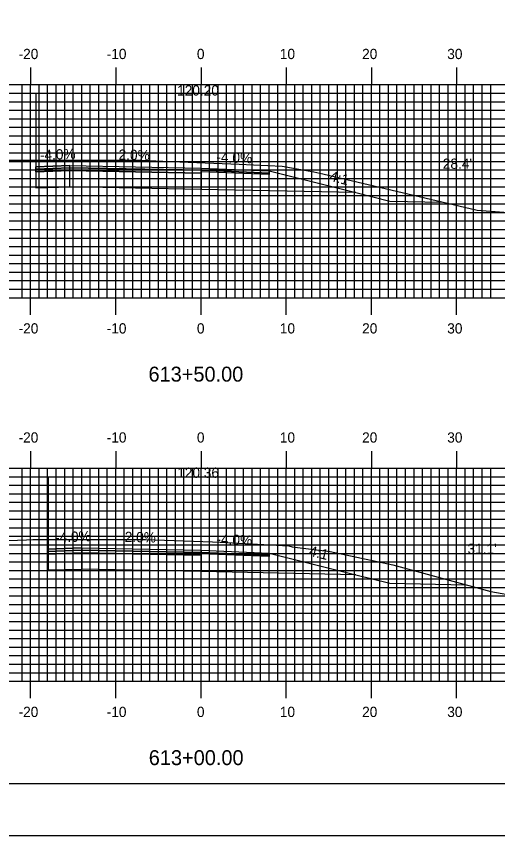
# Model space of a CAD drawing. Extents: x 844143 to 844486, y 363538 to 363758.
# Drawn here: x 844286.8 to 844343.3, y 363537.6 to 363633.7 of the extents above; entities that cross this region are included whole.
import ezdxf

# ---------------------------------------------------------------- set-up
doc = ezdxf.new("R2010")
doc.units = 0
for name, color, linetype in [('ANNOTATION', 7, 'Continuous'), ('BORDER', 7, 'Continuous'), ('D_Roadway_Centerline', 7, 'Continuous'), ('D_Roadway_Centerline_Text', 7, 'Continuous'), ('D_Roadway_Edge_Shoulder', 7, 'Continuous'), ('D_Roadway_Edge_TW', 7, 'Continuous'), ('D_Roadway_FinishedGrade', 7, 'Continuous'), ('D_Roadway_Pavement', 7, 'Continuous'), ('D_Roadway_SubGrade', 7, 'Continuous'), ('D_Text_Standard', 7, 'Continuous'), ('H_V ANNOTATION', 7, 'Continuous'), ('M_Roadway_Centerline', 7, 'Continuous'), ('MAJOR', 7, 'Continuous'), ('MINOR', 7, 'Continuous'), ('PLOT BOUNDARY', 7, 'Continuous'), ('S_Roadway_Centerline', 7, 'Continuous')]:
    doc.layers.add(name, color=color, linetype=linetype)

msp = doc.modelspace()

# ---------------------------------------------------------------- linework, layer by layer
at = {"layer": 'BORDER'}
msp.add_lwpolyline([(844158.85, 363543.721), (844478.85, 363543.721), (844478.85, 363753.721), (844158.85, 363753.721)], close=True, dxfattribs=at)
at = {"layer": 'D_Roadway_Centerline'}
for points in [[(844289.067, 363616.066), (844293.067, 363616.226), (844308.45, 363615.918), (844316.45, 363615.598), (844326.624, 363613.055)], [(844290.512, 363571.199), (844294.512, 363571.359), (844308.45, 363571.08), (844316.45, 363570.76), (844326.624, 363568.217)]]:
    msp.add_lwpolyline(points, dxfattribs=at)
at = {"layer": 'D_Roadway_Edge_Shoulder'}
for points in [[(844293.067, 363616.226), (844289.067, 363616.066), (844289.067, 363615.816), (844293.067, 363615.976)], [(844308.45, 363615.918), (844316.45, 363615.598), (844316.45, 363615.348), (844308.45, 363615.668)], [(844294.512, 363571.359), (844290.512, 363571.199), (844290.512, 363570.949), (844294.512, 363571.109)], [(844308.45, 363571.08), (844316.45, 363570.76), (844316.45, 363570.51), (844308.45, 363570.83)]]:
    msp.add_lwpolyline(points, close=True, dxfattribs=at)
at = {"layer": 'D_Roadway_Edge_TW'}
for points in [[(844293.067, 363616.226), (844308.45, 363615.918), (844308.45, 363615.668), (844293.067, 363615.976)], [(844294.512, 363571.359), (844308.45, 363571.08), (844308.45, 363570.83), (844294.512, 363571.109)]]:
    msp.add_lwpolyline(points, close=True, dxfattribs=at)
at = {"layer": 'D_Roadway_FinishedGrade'}
for points in [[(844326.624, 363613.055), (844330.624, 363612.055), (844336.808, 363611.931)], [(844326.624, 363568.217), (844330.624, 363567.217), (844339.574, 363567.038)]]:
    msp.add_lwpolyline(points, dxfattribs=at)
at = {"layer": 'D_Roadway_Pavement'}
for points in [[(844293.067, 363615.976), (844289.067, 363615.816), (844289.067, 363615.483), (844293.067, 363615.643)], [(844293.067, 363615.976), (844308.45, 363615.668), (844308.45, 363615.335), (844293.067, 363615.643)], [(844308.45, 363615.668), (844316.45, 363615.348), (844316.45, 363615.182), (844308.45, 363615.502)], [(844294.512, 363571.109), (844290.512, 363570.949), (844290.512, 363570.616), (844294.512, 363570.776)], [(844294.512, 363571.109), (844308.45, 363570.83), (844308.45, 363570.497), (844294.512, 363570.776)], [(844308.45, 363570.83), (844316.45, 363570.51), (844316.45, 363570.344), (844308.45, 363570.664)]]:
    msp.add_lwpolyline(points, close=True, dxfattribs=at)
for points in [[(844308.45, 363615.668), (844308.45, 363615.335)], [(844308.45, 363615.668), (844308.45, 363615.335)], [(844308.45, 363570.83), (844308.45, 363570.497)], [(844308.45, 363570.83), (844308.45, 363570.497)]]:
    msp.add_lwpolyline(points, dxfattribs=at)
at = {"layer": 'D_Roadway_SubGrade'}
for p, q in [((844289.067, 363624.724), (844289.067, 363613.626)), ((844290.512, 363579.713), (844290.512, 363568.616))]:
    msp.add_line(p, q, dxfattribs=at)
for points in [[(844293.067, 363615.643), (844289.067, 363615.483), (844289.067, 363615.816), (844289.067, 363616.066), (844289.067, 363613.626), (844293.067, 363613.726)], [(844293.067, 363615.643), (844308.45, 363615.335), (844308.45, 363613.418), (844293.067, 363613.726)], [(844308.45, 363615.335), (844308.45, 363615.668), (844316.45, 363615.348), (844316.45, 363615.598), (844326.624, 363613.055), (844308.45, 363613.418)], [(844294.512, 363570.776), (844290.512, 363570.616), (844290.512, 363570.949), (844290.512, 363571.199), (844290.512, 363568.779), (844294.512, 363568.859)], [(844294.512, 363570.776), (844308.45, 363570.497), (844308.45, 363568.58), (844294.512, 363568.859)], [(844308.45, 363570.497), (844308.45, 363570.83), (844316.45, 363570.51), (844316.45, 363570.76), (844326.624, 363568.217), (844308.45, 363568.58)]]:
    msp.add_lwpolyline(points, close=True, dxfattribs=at)
at = {"layer": 'MAJOR'}
for p, q in [((844288.45, 363627.725), (844288.45, 363625.721)), ((844298.45, 363627.725), (844298.45, 363625.721)), ((844308.45, 363627.725), (844308.45, 363625.721)), ((844318.45, 363627.725), (844318.45, 363625.721)), ((844328.45, 363627.725), (844328.45, 363625.721)), ((844338.45, 363627.725), (844338.45, 363625.721)), ((844168.45, 363625.721), (844448.45, 363625.721)), ((844168.45, 363625.721), (844448.45, 363625.721)), ((844288.45, 363600.721), (844288.45, 363625.721)), ((844298.45, 363600.721), (844298.45, 363625.721)), ((844308.45, 363600.721), (844308.45, 363625.721)), ((844318.45, 363600.721), (844318.45, 363625.721)), ((844328.45, 363600.721), (844328.45, 363625.721)), ((844338.45, 363600.721), (844338.45, 363625.721)), ((844168.45, 363620.721), (844448.45, 363620.721)), ((844168.45, 363615.721), (844448.45, 363615.721)), ((844168.45, 363610.721), (844448.45, 363610.721)), ((844168.45, 363605.721), (844448.45, 363605.721)), ((844168.45, 363600.721), (844448.45, 363600.721)), ((844168.45, 363600.721), (844448.45, 363600.721)), ((844288.45, 363598.717), (844288.45, 363600.721)), ((844298.45, 363598.717), (844298.45, 363600.721)), ((844308.45, 363598.717), (844308.45, 363600.721)), ((844318.45, 363598.717), (844318.45, 363600.721)), ((844328.45, 363598.717), (844328.45, 363600.721)), ((844338.45, 363598.717), (844338.45, 363600.721)), ((844288.45, 363582.725), (844288.45, 363580.721)), ((844298.45, 363582.725), (844298.45, 363580.721)), ((844308.45, 363582.725), (844308.45, 363580.721)), ((844318.45, 363582.725), (844318.45, 363580.721)), ((844328.45, 363582.725), (844328.45, 363580.721)), ((844338.45, 363582.725), (844338.45, 363580.721)), ((844168.45, 363580.721), (844448.45, 363580.721)), ((844168.45, 363580.721), (844448.45, 363580.721)), ((844288.45, 363555.721), (844288.45, 363580.721)), ((844298.45, 363555.721), (844298.45, 363580.721)), ((844308.45, 363555.721), (844308.45, 363580.721)), ((844318.45, 363555.721), (844318.45, 363580.721)), ((844328.45, 363555.721), (844328.45, 363580.721)), ((844338.45, 363555.721), (844338.45, 363580.721)), ((844168.45, 363575.721), (844448.45, 363575.721)), ((844168.45, 363570.721), (844448.45, 363570.721)), ((844168.45, 363565.721), (844448.45, 363565.721)), ((844168.45, 363560.721), (844448.45, 363560.721)), ((844168.45, 363555.721), (844448.45, 363555.721)), ((844168.45, 363555.721), (844448.45, 363555.721)), ((844288.45, 363553.717), (844288.45, 363555.721)), ((844298.45, 363553.717), (844298.45, 363555.721)), ((844308.45, 363553.717), (844308.45, 363555.721)), ((844318.45, 363553.717), (844318.45, 363555.721)), ((844328.45, 363553.717), (844328.45, 363555.721)), ((844338.45, 363553.717), (844338.45, 363555.721))]:
    msp.add_line(p, q, dxfattribs=at)
at = {"layer": 'MINOR'}
for p, q in [((844287.45, 363600.721), (844287.45, 363625.721)), ((844289.45, 363600.721), (844289.45, 363625.721)), ((844290.45, 363600.721), (844290.45, 363625.721)), ((844291.45, 363600.721), (844291.45, 363625.721)), ((844292.45, 363600.721), (844292.45, 363625.721)), ((844293.45, 363600.721), (844293.45, 363625.721)), ((844294.45, 363600.721), (844294.45, 363625.721)), ((844295.45, 363600.721), (844295.45, 363625.721)), ((844296.45, 363600.721), (844296.45, 363625.721)), ((844297.45, 363600.721), (844297.45, 363625.721)), ((844299.45, 363600.721), (844299.45, 363625.721)), ((844300.45, 363600.721), (844300.45, 363625.721)), ((844301.45, 363600.721), (844301.45, 363625.721)), ((844302.45, 363600.721), (844302.45, 363625.721)), ((844303.45, 363600.721), (844303.45, 363625.721)), ((844304.45, 363600.721), (844304.45, 363625.721)), ((844305.45, 363600.721), (844305.45, 363625.721)), ((844306.45, 363600.721), (844306.45, 363625.721)), ((844307.45, 363600.721), (844307.45, 363625.721)), ((844309.45, 363600.721), (844309.45, 363625.721)), ((844310.45, 363600.721), (844310.45, 363625.721)), ((844311.45, 363600.721), (844311.45, 363625.721)), ((844312.45, 363600.721), (844312.45, 363625.721)), ((844313.45, 363600.721), (844313.45, 363625.721)), ((844314.45, 363600.721), (844314.45, 363625.721)), ((844315.45, 363600.721), (844315.45, 363625.721)), ((844316.45, 363600.721), (844316.45, 363625.721)), ((844317.45, 363600.721), (844317.45, 363625.721)), ((844319.45, 363600.721), (844319.45, 363625.721)), ((844320.45, 363600.721), (844320.45, 363625.721)), ((844321.45, 363600.721), (844321.45, 363625.721)), ((844322.45, 363600.721), (844322.45, 363625.721)), ((844323.45, 363600.721), (844323.45, 363625.721)), ((844324.45, 363600.721), (844324.45, 363625.721)), ((844325.45, 363600.721), (844325.45, 363625.721)), ((844326.45, 363600.721), (844326.45, 363625.721)), ((844327.45, 363600.721), (844327.45, 363625.721)), ((844329.45, 363600.721), (844329.45, 363625.721)), ((844330.45, 363600.721), (844330.45, 363625.721)), ((844331.45, 363600.721), (844331.45, 363625.721)), ((844332.45, 363600.721), (844332.45, 363625.721)), ((844333.45, 363600.721), (844333.45, 363625.721)), ((844334.45, 363600.721), (844334.45, 363625.721)), ((844335.45, 363600.721), (844335.45, 363625.721)), ((844336.45, 363600.721), (844336.45, 363625.721)), ((844337.45, 363600.721), (844337.45, 363625.721)), ((844339.45, 363600.721), (844339.45, 363625.721)), ((844340.45, 363600.721), (844340.45, 363625.721)), ((844341.45, 363600.721), (844341.45, 363625.721)), ((844342.45, 363600.721), (844342.45, 363625.721)), ((844168.45, 363624.721), (844448.45, 363624.721)), ((844168.45, 363623.721), (844448.45, 363623.721)), ((844168.45, 363622.721), (844448.45, 363622.721)), ((844168.45, 363621.721), (844448.45, 363621.721)), ((844168.45, 363619.721), (844448.45, 363619.721)), ((844168.45, 363618.721), (844448.45, 363618.721)), ((844168.45, 363617.721), (844448.45, 363617.721)), ((844168.45, 363616.721), (844448.45, 363616.721)), ((844168.45, 363614.721), (844448.45, 363614.721)), ((844168.45, 363613.721), (844448.45, 363613.721)), ((844168.45, 363612.721), (844448.45, 363612.721)), ((844168.45, 363611.721), (844448.45, 363611.721)), ((844168.45, 363609.721), (844448.45, 363609.721)), ((844168.45, 363608.721), (844448.45, 363608.721)), ((844168.45, 363607.721), (844448.45, 363607.721)), ((844168.45, 363606.721), (844448.45, 363606.721)), ((844168.45, 363604.721), (844448.45, 363604.721)), ((844168.45, 363603.721), (844448.45, 363603.721)), ((844168.45, 363602.721), (844448.45, 363602.721)), ((844168.45, 363601.721), (844448.45, 363601.721)), ((844287.45, 363555.721), (844287.45, 363580.721)), ((844289.45, 363555.721), (844289.45, 363580.721)), ((844290.45, 363555.721), (844290.45, 363580.721)), ((844291.45, 363555.721), (844291.45, 363580.721)), ((844292.45, 363555.721), (844292.45, 363580.721)), ((844293.45, 363555.721), (844293.45, 363580.721)), ((844294.45, 363555.721), (844294.45, 363580.721)), ((844295.45, 363555.721), (844295.45, 363580.721)), ((844296.45, 363555.721), (844296.45, 363580.721)), ((844297.45, 363555.721), (844297.45, 363580.721)), ((844299.45, 363555.721), (844299.45, 363580.721)), ((844300.45, 363555.721), (844300.45, 363580.721)), ((844301.45, 363555.721), (844301.45, 363580.721)), ((844302.45, 363555.721), (844302.45, 363580.721)), ((844303.45, 363555.721), (844303.45, 363580.721)), ((844304.45, 363555.721), (844304.45, 363580.721)), ((844305.45, 363555.721), (844305.45, 363580.721)), ((844306.45, 363555.721), (844306.45, 363580.721)), ((844307.45, 363555.721), (844307.45, 363580.721)), ((844309.45, 363555.721), (844309.45, 363580.721)), ((844310.45, 363555.721), (844310.45, 363580.721)), ((844311.45, 363555.721), (844311.45, 363580.721)), ((844312.45, 363555.721), (844312.45, 363580.721)), ((844313.45, 363555.721), (844313.45, 363580.721)), ((844314.45, 363555.721), (844314.45, 363580.721)), ((844315.45, 363555.721), (844315.45, 363580.721)), ((844316.45, 363555.721), (844316.45, 363580.721)), ((844317.45, 363555.721), (844317.45, 363580.721)), ((844319.45, 363555.721), (844319.45, 363580.721)), ((844320.45, 363555.721), (844320.45, 363580.721)), ((844321.45, 363555.721), (844321.45, 363580.721)), ((844322.45, 363555.721), (844322.45, 363580.721)), ((844323.45, 363555.721), (844323.45, 363580.721)), ((844324.45, 363555.721), (844324.45, 363580.721)), ((844325.45, 363555.721), (844325.45, 363580.721)), ((844326.45, 363555.721), (844326.45, 363580.721)), ((844327.45, 363555.721), (844327.45, 363580.721)), ((844329.45, 363555.721), (844329.45, 363580.721)), ((844330.45, 363555.721), (844330.45, 363580.721)), ((844331.45, 363555.721), (844331.45, 363580.721)), ((844332.45, 363555.721), (844332.45, 363580.721)), ((844333.45, 363555.721), (844333.45, 363580.721)), ((844334.45, 363555.721), (844334.45, 363580.721)), ((844335.45, 363555.721), (844335.45, 363580.721)), ((844336.45, 363555.721), (844336.45, 363580.721)), ((844337.45, 363555.721), (844337.45, 363580.721)), ((844339.45, 363555.721), (844339.45, 363580.721)), ((844340.45, 363555.721), (844340.45, 363580.721)), ((844341.45, 363555.721), (844341.45, 363580.721)), ((844342.45, 363555.721), (844342.45, 363580.721)), ((844168.45, 363579.721), (844448.45, 363579.721)), ((844168.45, 363578.721), (844448.45, 363578.721)), ((844168.45, 363577.721), (844448.45, 363577.721)), ((844168.45, 363576.721), (844448.45, 363576.721)), ((844168.45, 363574.721), (844448.45, 363574.721)), ((844168.45, 363573.721), (844448.45, 363573.721)), ((844168.45, 363572.721), (844448.45, 363572.721)), ((844168.45, 363571.721), (844448.45, 363571.721)), ((844168.45, 363569.721), (844448.45, 363569.721)), ((844168.45, 363568.721), (844448.45, 363568.721)), ((844168.45, 363567.721), (844448.45, 363567.721)), ((844168.45, 363566.721), (844448.45, 363566.721)), ((844168.45, 363564.721), (844448.45, 363564.721)), ((844168.45, 363563.721), (844448.45, 363563.721)), ((844168.45, 363562.721), (844448.45, 363562.721)), ((844168.45, 363561.721), (844448.45, 363561.721)), ((844168.45, 363559.721), (844448.45, 363559.721)), ((844168.45, 363558.721), (844448.45, 363558.721)), ((844168.45, 363557.721), (844448.45, 363557.721)), ((844168.45, 363556.721), (844448.45, 363556.721))]:
    msp.add_line(p, q, dxfattribs=at)
at = {"layer": 'PLOT BOUNDARY'}
msp.add_lwpolyline([(844142.664, 363537.603), (844482.664, 363537.603), (844482.664, 363757.603), (844142.664, 363757.603)], close=True, dxfattribs=at)
at = {"layer": 'S_Roadway_Centerline'}
for points in [[(844285.11, 363616.862), (844289.276, 363616.87), (844300.655, 363616.861), (844301.219, 363616.847), (844301.372, 363616.842), (844302.344, 363616.802), (844303.974, 363616.728), (844312.933, 363616.389), (844317.969, 363616.148), (844321.674, 363615.48), (844322.761, 363615.244), (844340.853, 363610.977), (844351.335, 363610.201), (844352.946, 363609.972), (844353.329, 363609.949), (844353.335, 363609.98), (844353.674, 363609.984), (844355.793, 363610.329), (844359.11, 363610.818), (844362.894, 363611.365), (844376.838, 363613.615), (844381.112, 363613.913), (844387.785, 363613.939)], [(844277.253, 363571.913), (844287.976, 363572.308), (844288.699, 363572.337), (844299.814, 363572.345), (844300.456, 363572.348), (844301.703, 363572.351), (844301.931, 363572.329), (844309.784, 363572.079), (844310.696, 363572.043), (844318.775, 363571.615), (844319.138, 363571.502), (844323.619, 363570.934), (844330.951, 363569.372), (844342.48, 363566.232), (844348.642, 363565.15), (844354.919, 363565.244), (844366.62, 363567.514), (844368.496, 363568.092), (844373.315, 363568.864), (844382.329, 363570.725), (844386.68, 363570.832)]]:
    msp.add_lwpolyline(points, dxfattribs=at)

# ---------------------------------------------------------------- texts
at = {"layer": 'ANNOTATION'}
for s, rotation, p in [('-4.0%', 2.29061, (844289.562, 363616.853)), ('2.0%', 358.85424, (844298.766, 363616.913)), ('-4.0%', 357.70939, (844310.242, 363616.648)), ('4:1', 345.96376, (844323.457, 363614.45)), ('-4.0%', 2.29061, (844291.341, 363571.986)), ('2.0%', 358.85424, (844299.488, 363572.06)), ('-4.0%', 357.70939, (844310.242, 363571.81)), ('4:1', 345.96376, (844321.043, 363570.474))]:
    msp.add_text(s, height=1.2, rotation=rotation, dxfattribs=at).set_placement(p)
at = {"layer": 'D_Roadway_Centerline_Text'}
for s, p in [('120.20', (844305.646, 363624.445)), ('120.36', (844305.657, 363579.587))]:
    msp.add_text(s, height=1.2, dxfattribs=at).set_placement(p)
at = {"layer": 'D_Text_Standard'}
for s, p in [("28.4'", (844336.827, 363615.844)), ("31.1'", (844339.726, 363570.661))]:
    msp.add_text(s, height=1.2, dxfattribs=at).set_placement(p)
at = {"layer": 'H_V ANNOTATION'}
for s, height, p in [('-20', 1.2, (844287.037, 363628.721)), ('-10', 1.2, (844297.38, 363628.721)), ('0', 1.2, (844307.969, 363628.721)), ('10', 1.2, (844317.701, 363628.721)), ('20', 1.2, (844327.358, 363628.721)), ('30', 1.2, (844337.348, 363628.721)), ('-20', 1.2, (844287.037, 363596.521)), ('-10', 1.2, (844297.38, 363596.521)), ('0', 1.2, (844307.969, 363596.521)), ('10', 1.2, (844317.701, 363596.521)), ('20', 1.2, (844327.358, 363596.521)), ('30', 1.2, (844337.348, 363596.521)), ('613+50.00', 1.75, (844302.286, 363590.877)), ('-20', 1.2, (844287.037, 363583.721)), ('-10', 1.2, (844297.38, 363583.721)), ('0', 1.2, (844307.969, 363583.721)), ('10', 1.2, (844317.701, 363583.721)), ('20', 1.2, (844327.358, 363583.721)), ('30', 1.2, (844337.348, 363583.721)), ('-20', 1.2, (844287.037, 363551.521)), ('-10', 1.2, (844297.38, 363551.521)), ('0', 1.2, (844307.969, 363551.521)), ('10', 1.2, (844317.701, 363551.521)), ('20', 1.2, (844327.358, 363551.521)), ('30', 1.2, (844337.348, 363551.521)), ('613+00.00', 1.75, (844302.318, 363545.877))]:
    msp.add_text(s, height=height, dxfattribs=at).set_placement(p)
at = {"layer": 'M_Roadway_Centerline'}
for s, p in [('C', (844301.214, 363616.847)), ('L', (844301.219, 363616.839)), ('C', (844288.694, 363572.337)), ('L', (844288.699, 363572.33)), ('C', (844301.698, 363572.351)), ('L', (844301.703, 363572.344))]:
    msp.add_text(s, height=0.0146, dxfattribs=at).set_placement(p)

doc.saveas('drawing.dxf')
